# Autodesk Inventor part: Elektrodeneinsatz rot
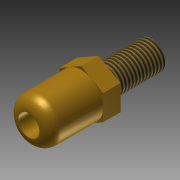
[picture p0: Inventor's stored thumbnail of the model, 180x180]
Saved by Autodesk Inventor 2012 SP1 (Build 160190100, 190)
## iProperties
Created: 2012-10
Part Number: Elektrodeneinsatz rot
Material: Default
Document SubType Name: Modeling
Designer: Dominic Mähling
Density: 1 g/cm^3
Author: Dominic Mähling
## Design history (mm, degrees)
derived "Funkenstrecke master.ipt"
feature "Elektrodeneinsatz rot::Funkenstrecke master.ipt" dims "d0" = 10
tag "Bezeichnung1"
node "Volumenkörper1"
other parameters: "sa_0" = 0, "sa_1" = 0, "sa_2" = 2e+07
